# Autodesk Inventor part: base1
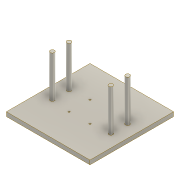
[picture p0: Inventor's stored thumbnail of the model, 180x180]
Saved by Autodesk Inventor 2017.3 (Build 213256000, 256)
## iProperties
Part Number: base1
Material: チタン
Document SubType Name: Modeling
Designer: kyushu-hep
Density: 4.51 g/cm^3
Appearance: チタン
Author: kyushu-hep
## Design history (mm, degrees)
sketch "スケッチ3"
  geometry: L1 (-100, 100)-(100, 100); L2 (100, 100)-(100, -100); L3 (100, -100)-(-100, -100); L4 (-100, -100)-(-100, 100); 1 further point
  constraints: 8 end point, 2 parallel, 1 horizontal, 1 perpendicular
  dimensions: "d19" = 100 distance from line of L1 point (0, 0); "d20" = 200 distance of L3.end L1.start; "d21" = 200 distance of L1.start L1.end; "d22" = 100 distance from line of L4 point (0, 0)
extrude "押し出し3" new body sketch "スケッチ3" distance "d23" = 10; taper "d24" = 0 deg
sketch "スケッチ4"
  geometry: C1 r 5 at (-70, 20); C2 r 5 at (-70, -20); C3 r 5 at (70, 20); C4 r 5 at (70, -20); 1 further point
  constraints: 4 centre point
  dimensions: "d52" = 10 diameter of C1; "d53" = 20 vertical distance of point (0, 0) C1.centre; "d54" = 70 horizontal distance of point (0, 0) C1.centre; "d55" = 10 diameter of C2; "d56" = 10 diameter of C3; "d57" = 10 diameter of C4; "d58" = 20 vertical distance of point (0, 0) C2.centre; "d59" = 70 horizontal distance of point (0, 0) C2.centre
sketch "スケッチ6"
  geometry: L1 (52, -52)-(-52, -52); L2 (-52, -52)-(-52, 52); L3 (-52, 52)-(52, 52); L4 (52, 52)-(52, -52); L5 (52, -52)-(-52, 52); L6 (-52, -52)-(52, 52); C1 r 2 at (-25, 25); C2 r 2 at (25, 25); C3 r 2 at (-25, -25); C4 r 2 at (25, -25); 1 further point
  constraints: 12 end point, 4 centre point, 2 horizontal, 2 midpoint, 2 parallel, 1 perpendicular, 1 vertical, 6 other
  dimensions: "d38" = 4 diameter of C1; "d40" = 25 horizontal distance of point (0, 0) C1.centre; "d43" = 50 distance of C1.centre C2.centre; "d46" = 50 distance of C1.centre C3.centre; "d51" = 25 horizontal distance of point (0, 0) C2.centre
extrude "押し出し6" cut sketch "スケッチ6" distance "d49" = 10; taper "d50" = 0 deg
extrude "押し出し7" join sketch "スケッチ4" distance "d60" = 100; taper "d61" = 0 deg
node "ソリッド2"
